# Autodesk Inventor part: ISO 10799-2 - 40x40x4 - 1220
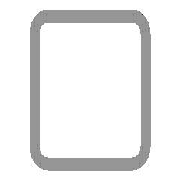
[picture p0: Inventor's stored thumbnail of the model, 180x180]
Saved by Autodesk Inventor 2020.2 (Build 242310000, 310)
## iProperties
Created: 2019-01
Part Number: ISO 10799-2 - 40x40x4 - 1220
Material: Steel, Mild
Description: Structural steels - Cold-formed, welded, structural hollow sections
Document SubType Name: Modeling
Standard: ISO
Designer: thira
Standard Revision: First edition 2011-09-15
Standards Organization: ISO
Language: en-US
Size Designation: 40x40x4
Categories: <MemberInstance><Categories><Category DisplayName="Structural Shapes" InternalName="089c4875-fa83-4c05-b084-43b9cc11f5ed" Mnemonic="GRDR"><CategoryParameter Dis
Stock Number: 40x40x4
Density: 7.85 g/cm^3
Appearance: Semi-Polished
_CCFamilyMember: 11
_CCFamilyDisplayName: ISO 10799-2 (Square) - Structural steels - Cold-formed, welded, structural hollow sections
_FrameMemberDoc: Frame Member File
_Version: 15.0.0
_GetPNFromCC: 1
G_L: 1220.000 mm
G_W: 40.000 mm
G_H: 40.000 mm
IsCustomPart: 1
Author: thira
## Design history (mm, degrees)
node "Start Plane"
node "End Plane"
sketch "Sketch"
  geometry: L1 (-20, -12)-(-20, 12); L2 (-12, 20)-(12, 20); L3 (20, 12)-(20, -12); L4 (12, -20)-(-12, -20); L5 (-12, 16)-(12, 16); L6 (16, 12)-(16, -12); L7 (12, -16)-(-12, -16); L8 (-16, -12)-(-16, 12); L9 (0, 30.32)-(0, -30.32) reference; L10 (-30.32, 0)-(30.32, 0) reference; A1 r 8 centre (-12, -12) between (-20, -12) and (-12, -20); A2 r 8 centre (12, 12) between (20, 12) and (12, 20); A3 r 8 centre (-12, 12) between (-12, 20) and (-20, 12); A4 r 8 centre (12, -12) between (12, -20) and (20, -12); A5 r 4 centre (-12, 12) between (-12, 16) and (-16, 12); A6 r 4 centre (12, 12) between (16, 12) and (12, 16); A7 r 4 centre (12, -12) between (12, -16) and (16, -12); A8 r 4 centre (-12, -12) between (-16, -12) and (-12, -16)
  constraints: 16 end point, 16 point on circle, 8 centre point, 8 tangent, 4 parallel, 3 equal radius, 2 perpendicular, 7 other
  dimensions: "d7" = 8 radius of A1 (= G_IR); "d9" = 40 distance between parallel lines of L1 L3 (= G_W); "d11" = 40 distance between parallel lines of L2 L4 (= G_H); "d12" = 4 distance between parallel lines of L3 L6 (= G_T); "d15" = 20 distance between parallel lines of L9 L3 (= 0.5 x d9); "d16" = 20 distance between parallel lines of L2 L10 (= 0.5 x d11)
extrude "Body" new body sketch "Sketch" stored distance "d3" = 1220 (= G_L); taper "d4" = 0 deg
node "Driven Length"
  sketch "Sketch3"
    geometry: L1 (0, 0)-(10, 0) reference
    constraints: 2 end point, 1 horizontal
  workplane "Work Plane3"
  sketch "Sketch4"
    geometry: L1 (-2, -20)-(12, -20) reference; L2 (-2, 1200)-(12, 1200) reference
    dimensions: "d18" = 1220 distance between parallel lines of L1 L2 (derived)
body "Solid1"
other parameters: "G_W" = 40 [user parameter; used in 1 equation term], "G_H" = 40 [user parameter; used in 1 equation term], "G_T" = 4 [user parameter; used in 1 equation term], "G_IR" = 8 [user parameter; used in 1 equation term], "G_L" = 1220 (= d18) [user parameter; used in 1 equation term], "G_OFFSET_END" = 0 [user parameter; used in 1 equation term], "d17" = 90 deg, "MAS" = 0.42 [user parameter]
